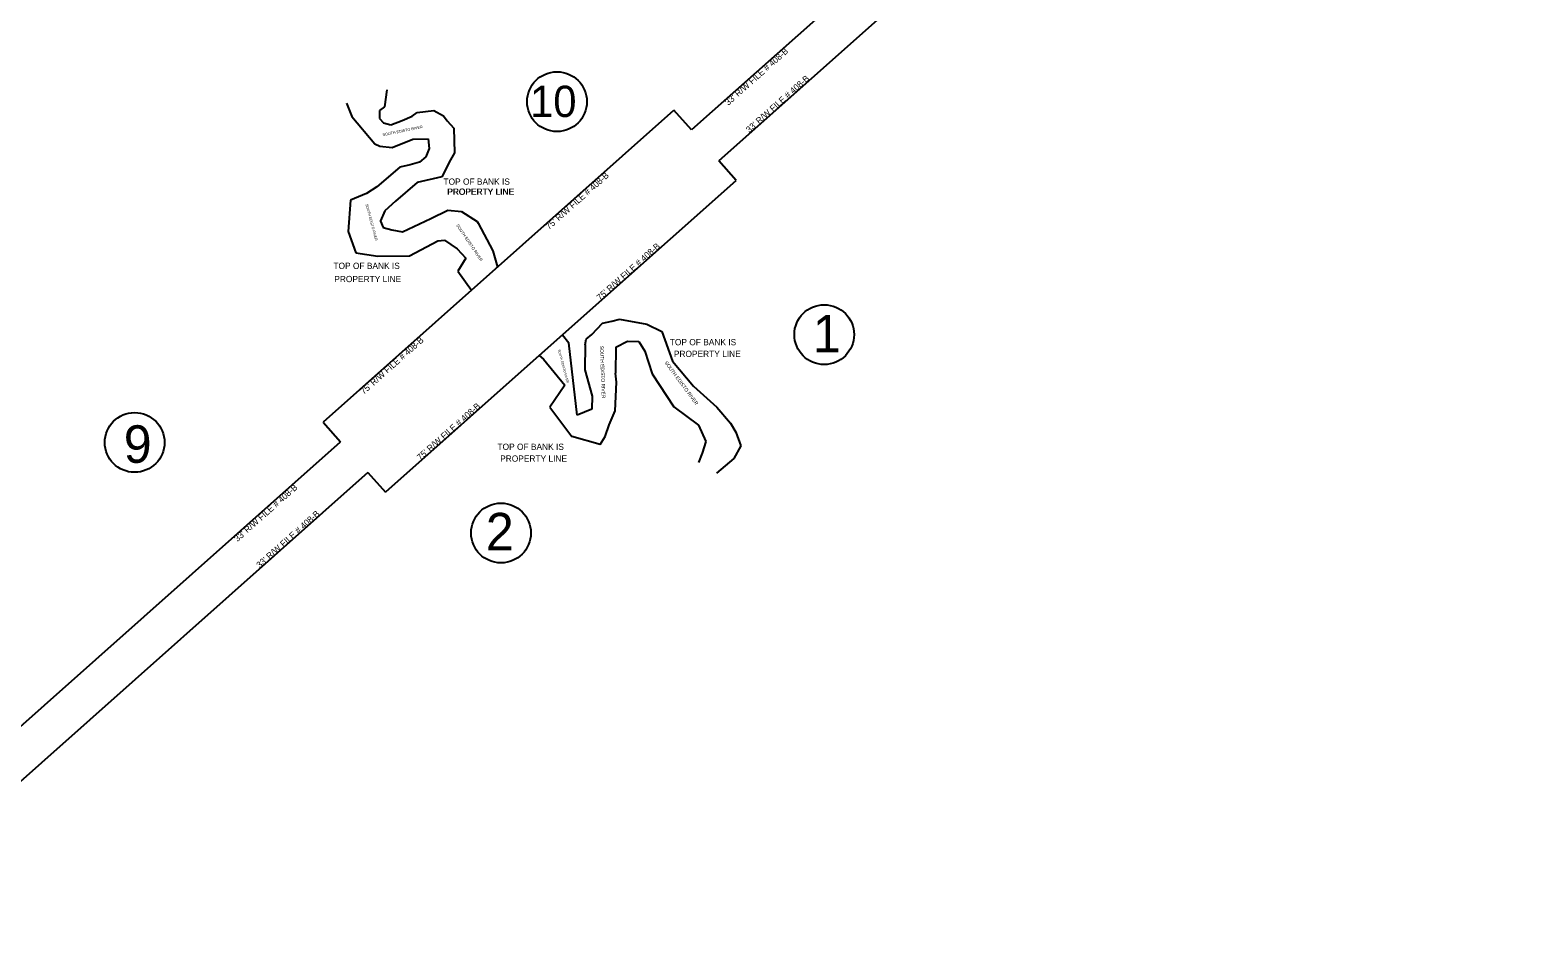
# Model space of a CAD drawing. Extents: x 50032 to 55703, y 49604 to 53496.
# Drawn here: x 52867 to 55280, y 50659 to 52114 of the extents above; entities that cross this region are included whole.
import ezdxf

# ---------------------------------------------------------------- set-up
doc = ezdxf.new("R2010")
doc.units = 0
doc.layers.add('Level 12', color=7, linetype='Continuous')
doc.layers.add('Level 25', color=7, linetype='Continuous')

msp = doc.modelspace()

# ---------------------------------------------------------------- linework, layer by layer
at = {"layer": 'Level 12'}
for p, q in [((55279.5, 53070), (53969, 51905.1)), ((54949.4, 52864.8), (53925.2, 51954.4)), ((53437.9, 52018.8), (53434.1, 51991.6)), ((53373.2, 51997), (53382, 51975.7)), ((53434.1, 51991.6), (53426.3, 51985.7)), ((53382, 51975.7), (53418.6, 51932.3)), ((53426.3, 51985.7), (53426.2, 51972.8)), ((53426.2, 51972.8), (53432.7, 51965.9)), ((53432.7, 51965.9), (53444.5, 51962.8)), ((53444.5, 51962.8), (53462.6, 51969.4)), ((53462.6, 51969.4), (53478.2, 51976.3)), ((53478.2, 51976.3), (53486.3, 51982.1)), ((53486.3, 51982.1), (53513, 51985.4)), ((53513, 51985.4), (53528.5, 51977.1)), ((53528.5, 51977.1), (53534.6, 51969)), ((53534.6, 51969), (53544.8, 51957.4)), ((53573.5, 51698), (53897.3, 51985.8)), ((53925.2, 51954.4), (53897.3, 51985.8)), ((53446.4, 51926.4), (53479.4, 51939.6)), ((53479.4, 51939.6), (53504.1, 51940.3)), ((53504.1, 51940.3), (53505.7, 51924.9)), ((53544.8, 51957.4), (53545.9, 51917.5)), ((53418.6, 51932.3), (53426.5, 51928.3)), ((53426.5, 51928.3), (53446.4, 51926.4)), ((53505.7, 51924.9), (53500, 51911.4)), ((53545.9, 51917.5), (53539.7, 51906.8)), ((53458.8, 51894.6), (53422, 51863.1)), ((53475.2, 51898.5), (53458.8, 51894.6)), ((53490.1, 51902.7), (53475.2, 51898.5)), ((53500, 51911.4), (53490.1, 51902.7)), ((53539.7, 51906.8), (53525.7, 51879.6)), ((53996.9, 51873.7), (53969, 51905.1)), ((53486.5, 51870.1), (53451.6, 51840.2)), ((53525.7, 51879.6), (53486.5, 51870.1)), ((53681.6, 51593.4), (53996.9, 51873.7)), ((53405.3, 51852.8), (53379.5, 51842.2)), ((53422, 51863.1), (53405.3, 51852.8)), ((53379.5, 51842.2), (53376.1, 51792.1)), ((53434.9, 51824.9), (53427.5, 51809.2)), ((53451.6, 51840.2), (53434.9, 51824.9)), ((53508.2, 51812.5), (53535.3, 51826)), ((53535.3, 51826), (53557.1, 51824.1)), ((53557.1, 51824.1), (53582.6, 51807.8)), ((53427.5, 51809.2), (53427.7, 51808.4)), ((53427.7, 51808.4), (53432.2, 51798.5)), ((53432.2, 51798.5), (53446.1, 51794.3)), ((53446.1, 51794.3), (53463.1, 51791.2)), ((53463.1, 51791.2), (53508.2, 51812.5)), ((53582.6, 51807.8), (53584, 51805)), ((53584, 51805), (53607.7, 51761.1)), ((53376.1, 51792.1), (53388.4, 51757.7)), ((53474.1, 51752.9), (53519.4, 51777.2)), ((53519.4, 51777.2), (53530.2, 51777.9)), ((53530.2, 51777.9), (53550.6, 51763.9)), ((53388.4, 51757.7), (53423.2, 51752.4)), ((53423.2, 51752.4), (53474.1, 51752.9)), ((53550.6, 51763.9), (53564.3, 51749.1)), ((53564.3, 51749.1), (53551.3, 51728.3)), ((53607.7, 51761.1), (53614.8, 51734.8)), ((53551.3, 51728.3), (53573.5, 51698)), ((53573.5, 51698), (53335.9, 51486.9)), ((53797.7, 51648.6), (53809.9, 51651.8)), ((53809.9, 51651.8), (53854.1, 51643.5)), ((53719, 51626.6), (53729.3, 51613.8)), ((53756.6, 51619.9), (53765.9, 51627.2)), ((53765.9, 51627.2), (53782.7, 51645)), ((53782.7, 51645), (53797.7, 51648.6)), ((53854.1, 51643.5), (53877.8, 51631.7)), ((53877.8, 51631.7), (53894.7, 51584.3)), ((53742.2, 51498), (53729.3, 51613.8)), ((53755.2, 51610.4), (53754.9, 51570.5)), ((53755.2, 51610.4), (53756.6, 51619.9)), ((53804.5, 51606.7), (53803.8, 51565.4)), ((53804.5, 51606.7), (53822.9, 51616.2)), ((53822.9, 51616.2), (53840.8, 51616)), ((53840.8, 51616), (53850.8, 51600.6)), ((53681.6, 51593.4), (53435.6, 51374.8)), ((53681.6, 51593.4), (53688.4, 51587.8)), ((53688.4, 51587.8), (53722.6, 51545.9)), ((53850.8, 51600.6), (53862.3, 51564)), ((53894.7, 51584.3), (53928.4, 51544.2)), ((53754.9, 51570.5), (53766.2, 51528.7)), ((53805.3, 51551.1), (53803.8, 51565.4)), ((53862.3, 51564), (53896.8, 51511.3)), ((53722.6, 51545.9), (53698.6, 51510.8)), ((53803.1, 51505.2), (53805.3, 51551.1)), ((53928.4, 51544.2), (53965.7, 51511)), ((53698.6, 51510.8), (53733.8, 51464)), ((53766, 51507.8), (53742.2, 51498)), ((53766.2, 51528.7), (53766, 51507.8)), ((53793.6, 51482.7), (53803.1, 51505.2)), ((53896.8, 51511.3), (53936.4, 51482.3)), ((53965.7, 51511), (53987.6, 51485.4)), ((53335.9, 51486.9), (53363.9, 51455.5)), ((53787.3, 51463.8), (53793.6, 51482.7)), ((53936.4, 51482.3), (53948, 51455.7)), ((53987.6, 51485.4), (53996.1, 51470.6)), ((53779, 51451.3), (53733.8, 51464)), ((53779, 51451.3), (53787.3, 51463.8)), ((53996.1, 51470.6), (54004.1, 51448.8)), ((52637.4, 50809.7), (53363.9, 51455.5)), ((53942.3, 51437.2), (53936.7, 51422.3)), ((53948, 51455.7), (53942.3, 51437.2)), ((54004.1, 51448.8), (53992.9, 51428.6)), ((53992.9, 51428.6), (53965.4, 51405.5)), ((53407.7, 51406.2), (52566.7, 50658.6)), ((53407.7, 51406.2), (53435.6, 51374.8))]:
    msp.add_line(p, q, dxfattribs=at)
at = {"layer": 'Level 25'}
for centre in [(53710.1, 51999.6), (54137.7, 51626.9), (53034.3, 51454.4), (53620.5, 51309.5)]:
    msp.add_circle(centre, 47.8, dxfattribs=at)

# ---------------------------------------------------------------- texts
for s, height, rotation, p in [("33' R/W FILE # 408-B", 10, 41.6333, (53984.2, 51992.9)), ("33' R/W FILE # 408-B", 10, 41.6333, (54017.8, 51949.2)), ('SOUTH EDISTO RIVER', 4.371, 11.5311, (53431.5, 51944.3)), ("75' R/W FILE # 408-B", 10, 41.6333, (53697.3, 51794.1)), ('SOUTH EDISTO RIVER', 4.047, 284.8841, (53403.7, 51835.3)), ('SOUTH EDISTO RIVER', 4.673, 304.097, (53548.5, 51801.7)), ("75' R/W FILE # 408-B", 10, 41.6333, (53779.1, 51680.8)), ("75' R/W FILE # 408-B", 10, 41.6333, (53400.9, 51530.6)), ('SOUTH EDISTO RIVER', 3.704, 284.9634, (53711.4, 51602.7)), ('SOUTH EDISTO RIVER', 5.621, 272.1197, (53778.8, 51608.9)), ('SOUTH EDISTO RIVER', 5.682, 306.3486, (53881.8, 51581.9)), ("75' R/W FILE # 408-B", 10, 41.6333, (53491.4, 51425)), ("33' R/W FILE # 408-B", 10, 41.6333, (53199, 51294.9)), ("33' R/W FILE # 408-B", 10, 41.6333, (53234.4, 51252.8))]:
    msp.add_text(s, height=height, rotation=rotation, dxfattribs=at).set_placement(p)
for s, height, p in [('10', 50, (53667, 51975.1)), ('TOP OF BANK IS', 10, (53528.5, 51866.7)), ('PROPERTY LINE', 10, (53534.2, 51850.6)), ('PROPERTY LINE', 10, (53534.9, 51850.6)), ('TOP OF BANK IS', 10, (53352.4, 51732)), ('PROPERTY LINE', 10, (53353.8, 51710.9)), ('1', 60, (54119.6, 51598.4)), ('TOP OF BANK IS', 10, (53890.6, 51609.9)), ('PROPERTY LINE', 10, (53897.1, 51591.1)), ('9', 60, (53016.9, 51421.8)), ('TOP OF BANK IS', 10, (53614.9, 51442.5)), ('PROPERTY LINE', 10, (53619.2, 51423.6)), ('2', 60, (53596.3, 51281.7))]:
    msp.add_text(s, height=height, dxfattribs=at).set_placement(p)

doc.saveas('drawing.dxf')
